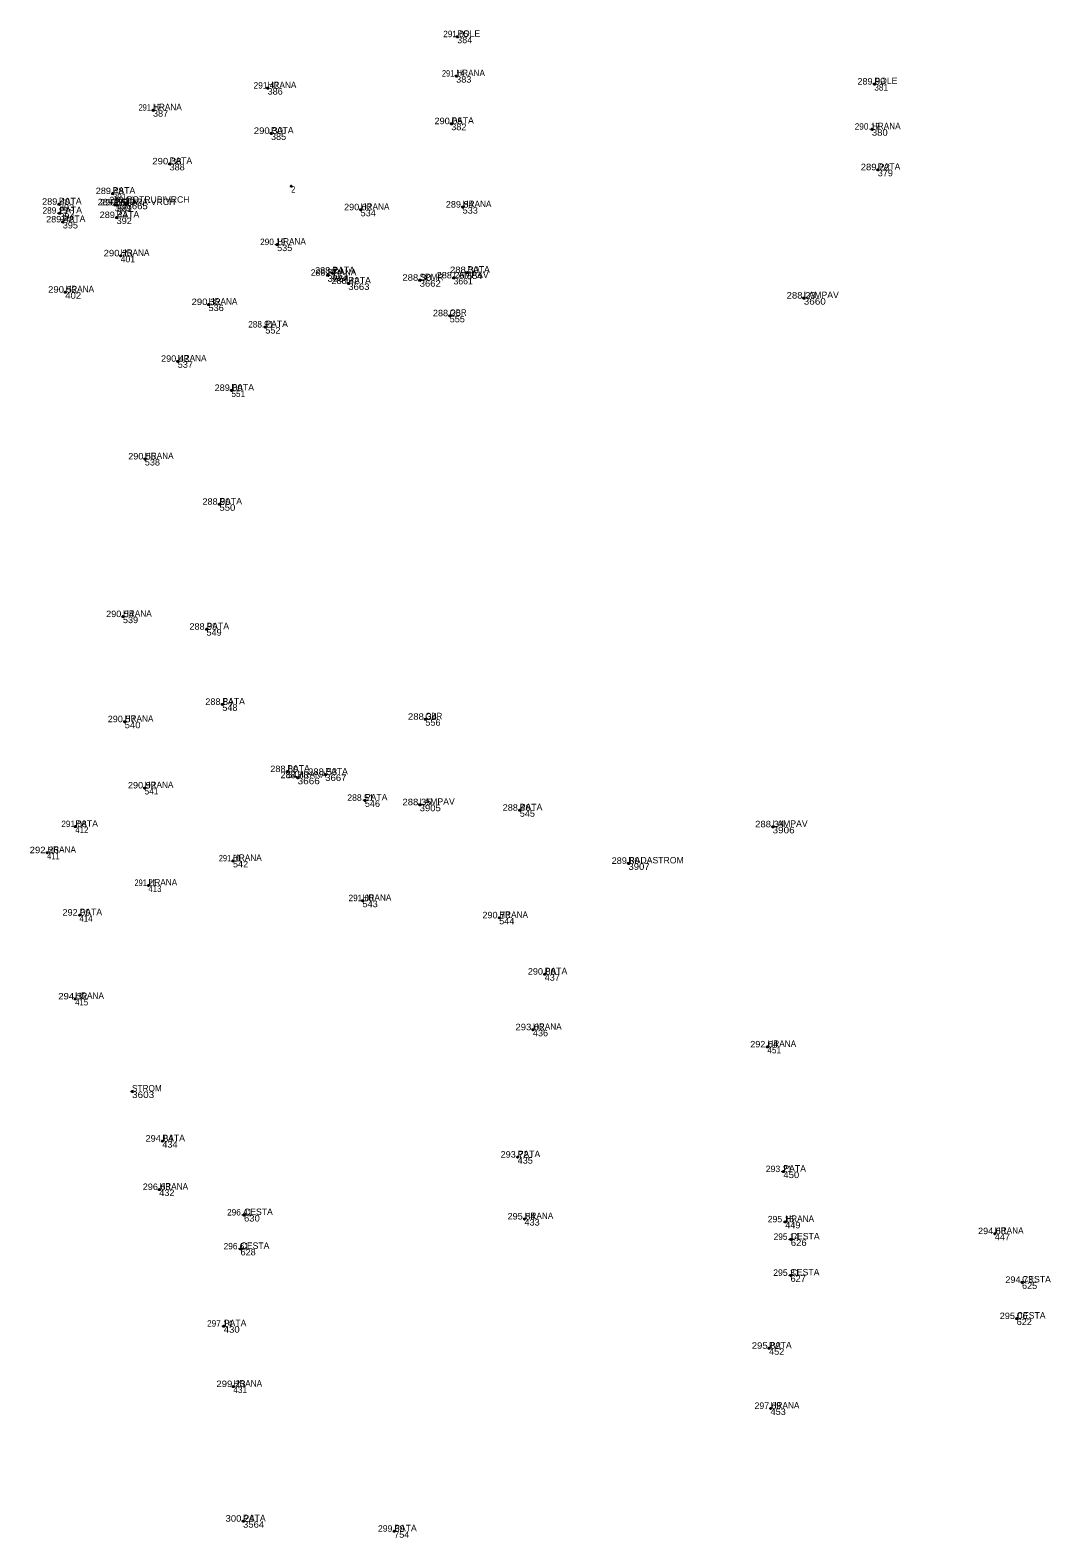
# Model space of a CAD drawing. Extents: x -565336 to -561834, y -1146819 to -1145270.
# Drawn here: x -563802.8 to -563749.2, y -1145852.4 to -1145773.2 of the extents above; entities that cross this region are included whole.
import ezdxf
from ezdxf.enums import TextEntityAlignment as Align

# ---------------------------------------------------------------- set-up
doc = ezdxf.new("R2010")
doc.units = 0
doc.header["$LTSCALE"] = 0.14
doc.header["$PDMODE"] = 32
doc.header["$PDSIZE"] = 0.07
for name, color, linetype in [('40', 7, 'Continuous'), ('43', 7, 'Continuous'), ('44', 7, 'Continuous'), ('45', 7, 'Continuous')]:
    doc.layers.add(name, color=color, linetype=linetype)

msp = doc.modelspace()

# ---------------------------------------------------------------- linework, layer by layer
at = {"layer": '40'}
for p in [(-563780.35, -1145773.53), (-563780.4, -1145775.6), (-563790.31, -1145776.23), (-563758.43, -1145776.02), (-563796.33, -1145777.39), (-563790.13, -1145778.61), (-563780.66, -1145778.1), (-563758.56, -1145778.39), (-563795.46, -1145780.21), (-563758.25, -1145780.52), (-563798.45, -1145781.77), (-563789.07, -1145781.38), (-563801.27, -1145782.33), (-563798.35, -1145782.36), (-563798.24, -1145782.37), (-563797.72, -1145782.25), (-563785.42, -1145782.62), (-563780.06, -1145782.48), (-563801.25, -1145782.8), (-563801.07, -1145783.26), (-563798.24, -1145783.03), (-563798.03, -1145785.04), (-563789.81, -1145784.45), (-563779.82, -1145785.92), (-563787.16, -1145786.06), (-563786.91, -1145785.95), (-563786.07, -1145786.49), (-563782.32, -1145786.32), (-563780.54, -1145786.2), (-563800.94, -1145786.95), (-563762.14, -1145787.26), (-563793.41, -1145787.6), (-563780.74, -1145788.19), (-563790.43, -1145788.78), (-563795.03, -1145790.58), (-563792.21, -1145792.11), (-563796.76, -1145795.71), (-563792.84, -1145798.09), (-563797.91, -1145803.99), (-563793.52, -1145804.65), (-563792.69, -1145808.6), (-563797.82, -1145809.51), (-563782.02, -1145809.38), (-563789.28, -1145812.13), (-563788.73, -1145812.45), (-563787.28, -1145812.28), (-563796.77, -1145812.99), (-563785.2, -1145813.64), (-563782.32, -1145813.87), (-563777.06, -1145814.16), (-563800.41, -1145815.02), (-563763.78, -1145815.03), (-563801.89, -1145816.39), (-563792.13, -1145816.82), (-563771.35, -1145816.95), (-563796.57, -1145818.11), (-563785.32, -1145818.91), (-563800.19, -1145819.67), (-563778.14, -1145819.81), (-563775.75, -1145822.77), (-563800.42, -1145824.07), (-563776.37, -1145825.69), (-563764.05, -1145826.59), (-563797.43, -1145828.93), (-563795.84, -1145831.54), (-563777.17, -1145832.38), (-563763.21, -1145833.14), (-563796, -1145834.08), (-563791.55, -1145835.42), (-563776.81, -1145835.63), (-563763.11, -1145835.78), (-563752.1, -1145836.4), (-563791.73, -1145837.2), (-563762.82, -1145836.7), (-563762.83, -1145838.59), (-563750.67, -1145838.96), (-563792.61, -1145841.26), (-563750.95, -1145840.86), (-563763.96, -1145842.42), (-563792.11, -1145844.43), (-563763.88, -1145845.58), (-563791.6, -1145851.5), (-563783.66, -1145852.03)]:
    msp.add_point(p, dxfattribs=at)

# ---------------------------------------------------------------- texts
at = {"layer": '43'}
for s, width, p in [('384', 1.05, (-563780.35, -1145773.87)), ('383', 1.05, (-563780.4, -1145775.94)), ('386', 1.05, (-563790.31, -1145776.57)), ('381', 0.95, (-563758.43, -1145776.36)), ('387', 1.05, (-563796.33, -1145777.73)), ('385', 1.05, (-563790.13, -1145778.95)), ('382', 1.05, (-563780.66, -1145778.44)), ('380', 1.1, (-563758.56, -1145778.73)), ('388', 1.05, (-563795.46, -1145780.55)), ('379', 1.05, (-563758.25, -1145780.86)), ('391', 0.95, (-563798.45, -1145782.11)), ('2', 0.75, (-563789.07, -1145781.72)), ('393', 1.05, (-563801.27, -1145782.67)), ('390', 1.1, (-563798.35, -1145782.7)), ('389', 1.05, (-563798.24, -1145782.71)), ('3665', 1.1, (-563797.72, -1145782.59)), ('534', 1.05, (-563785.42, -1145782.96)), ('533', 1.05, (-563780.06, -1145782.82)), ('394', 1.05, (-563801.25, -1145783.14)), ('395', 1.05, (-563801.07, -1145783.6)), ('392', 1.05, (-563798.24, -1145783.37)), ('535', 1.05, (-563789.81, -1145784.79)), ('3664', 1.1, (-563787.16, -1145786.4)), ('553', 1.05, (-563786.91, -1145786.29)), ('3663', 1.1, (-563786.07, -1145786.83)), ('3662', 1.1, (-563782.32, -1145786.66)), ('554', 1.05, (-563779.82, -1145786.26)), ('402', 1.1, (-563800.94, -1145787.29)), ('3660', 1.15, (-563762.14, -1145787.6)), ('536', 1.05, (-563793.41, -1145787.94)), ('555', 1.05, (-563780.74, -1145788.53)), ('552', 1.05, (-563790.43, -1145789.12)), ('537', 1.05, (-563795.03, -1145790.92)), ('551', 0.95, (-563792.21, -1145792.45)), ('538', 1.05, (-563796.76, -1145796.05)), ('550', 1.1, (-563792.84, -1145798.43)), ('539', 1.05, (-563797.91, -1145804.33)), ('549', 1.05, (-563793.52, -1145804.99)), ('548', 1.05, (-563792.69, -1145808.94)), ('540', 1.1, (-563797.82, -1145809.85)), ('556', 1.05, (-563782.02, -1145809.72)), ('547', 1.05, (-563789.28, -1145812.47)), ('3666', 1.15, (-563788.73, -1145812.79)), ('3667', 1.1, (-563787.28, -1145812.62)), ('541', 0.95, (-563796.77, -1145813.33)), ('546', 1.05, (-563785.2, -1145813.98)), ('3905', 1.1, (-563782.32, -1145814.21)), ('545', 1.05, (-563777.06, -1145814.5)), ('412', 0.9, (-563800.41, -1145815.36)), ('3906', 1.15, (-563763.78, -1145815.37)), ('411', 0.8, (-563801.89, -1145816.73)), ('542', 1.05, (-563792.13, -1145817.16)), ('3907', 1.1, (-563771.35, -1145817.29)), ('413', 0.9, (-563796.57, -1145818.45)), ('543', 1.05, (-563785.32, -1145819.25)), ('414', 0.9, (-563800.19, -1145820.01)), ('544', 1.05, (-563778.14, -1145820.15)), ('437', 1.05, (-563775.75, -1145823.11)), ('415', 0.9, (-563800.42, -1145824.41)), ('436', 1.05, (-563776.37, -1145826.03)), ('451', 0.95, (-563764.05, -1145826.93)), ('3603', 1.15, (-563797.43, -1145829.27)), ('434', 1.05, (-563795.84, -1145831.88)), ('435', 1.05, (-563777.17, -1145832.72)), ('450', 1.1, (-563763.21, -1145833.48)), ('432', 1.05, (-563796, -1145834.42)), ('630', 1.1, (-563791.55, -1145835.76)), ('433', 1.05, (-563776.81, -1145835.97)), ('449', 1.05, (-563763.11, -1145836.12)), ('447', 1.05, (-563752.1, -1145836.74)), ('628', 1.05, (-563791.73, -1145837.54)), ('626', 1.1, (-563762.82, -1145837.04)), ('627', 1.05, (-563762.83, -1145838.93)), ('625', 1.05, (-563750.67, -1145839.3)), ('430', 1.1, (-563792.61, -1145841.6)), ('622', 1.05, (-563750.95, -1145841.2)), ('452', 1.05, (-563763.96, -1145842.76)), ('431', 0.95, (-563792.11, -1145844.77)), ('453', 1.05, (-563763.88, -1145845.92)), ('3564', 1.1, (-563791.6, -1145851.84)), ('754', 1.05, (-563783.66, -1145852.37))]:
    msp.add_text(s, height=0.34, dxfattribs=dict(at, width=width)).set_placement(p)
for s, p in [('401', (-563798.03, -1145785.38)), ('3661', (-563780.54, -1145786.54))]:
    msp.add_text(s, height=0.34, dxfattribs=at).set_placement(p)
at = {"layer": '44'}
for s, width, p in [('291.05', 0.95, (-563780.421, -1145773.554)), ('291.14', 0.85, (-563780.5555, -1145775.624)), ('291.42', 0.95, (-563790.381, -1145776.254)), ('289.99', 1.05, (-563758.5905, -1145776.044)), ('291.17', 0.85, (-563796.4935, -1145777.414)), ('290.05', 1.05, (-563780.806, -1145778.124)), ('290.30', 1.1, (-563790.268, -1145778.634)), ('290.17', 0.95, (-563758.7985, -1145778.414)), ('290.38', 1.1, (-563795.5995, -1145780.234)), ('289.22', 1.1, (-563758.3815, -1145780.544)), ('289.48', 1.05, (-563798.6065, -1145781.794)), ('290.16', 0.95, (-563797.9505, -1145782.274)), ('289.40', 1.05, (-563801.4255, -1145782.354)), ('289.15', 0.95, (-563801.471, -1145782.824)), ('289.06', 1.05, (-563798.5055, -1145782.384)), ('289.44', 1.05, (-563798.4005, -1145783.054)), ('290.28', 1.05, (-563798.382, -1145782.394)), ('290.02', 1.05, (-563785.5605, -1145782.644)), ('289.84', 1.05, (-563780.2155, -1145782.504)), ('289.42', 1.05, (-563801.216, -1145783.284)), ('290.19', 0.95, (-563790.0405, -1145784.474)), ('290.23', 1.1, (-563798.1585, -1145785.064)), ('288.74', 1.05, (-563787.0845, -1145785.974)), ('288.26', 1.05, (-563780.6915, -1145786.224)), ('288.30', 1.1, (-563779.9635, -1145785.944)), ('290.52', 1.1, (-563801.0765, -1145786.974)), ('288.42', 1.05, (-563786.2215, -1145786.514)), ('288.30', 1.1, (-563782.4635, -1145786.344)), ('290.32', 1.1, (-563793.5385, -1145787.624)), ('288.23', 1.1, (-563762.274, -1145787.284)), ('288.26', 1.05, (-563780.8915, -1145788.214)), ('288.91', 0.95, (-563790.666, -1145788.804)), ('290.42', 1.05, (-563795.176, -1145790.604)), ('289.00', 1.05, (-563792.36, -1145792.134)), ('290.55', 1.05, (-563796.902, -1145795.734)), ('288.90', 1.05, (-563793.001, -1145798.114)), ('290.54', 1.05, (-563798.0615, -1145804.014)), ('288.99', 1.05, (-563793.686, -1145804.674)), ('288.84', 1.05, (-563792.851, -1145808.624)), ('290.57', 1.05, (-563797.9795, -1145809.534)), ('288.34', 1.1, (-563782.169, -1145809.404)), ('288.80', 1.05, (-563789.4355, -1145812.154)), ('288.53', 1.1, (-563787.4195, -1145812.304)), ('290.92', 1.05, (-563796.916, -1145813.014)), ('288.78', 1.05, (-563788.9005, -1145812.474)), ('288.35', 1.1, (-563782.4595, -1145813.894)), ('288.46', 1.05, (-563777.226, -1145814.184)), ('291.08', 0.95, (-563800.4865, -1145815.044)), ('288.34', 1.1, (-563763.929, -1145815.054)), ('292.26', 1.1, (-563802.0455, -1145816.414)), ('291.01', 0.85, (-563792.28, -1145816.844)), ('289.80', 1.05, (-563771.5, -1145816.974)), ('291.21', 0.85, (-563796.7105, -1145818.134)), ('291.00', 0.95, (-563785.395, -1145818.934)), ('292.09', 1.05, (-563800.355, -1145819.694)), ('290.73', 1.05, (-563778.2915, -1145819.834)), ('290.86', 1.05, (-563775.9055, -1145822.794)), ('294.32', 1.1, (-563800.543, -1145824.094)), ('293.02', 1.1, (-563776.5225, -1145825.714)), ('292.64', 1.05, (-563764.22, -1145826.614)), ('294.84', 1.05, (-563795.99, -1145831.564)), ('293.72', 1.05, (-563777.336, -1145832.404)), ('296.63', 1.05, (-563796.138, -1145834.104)), ('296.41', 0.95, (-563791.775, -1145835.444)), ('295.84', 1.05, (-563776.9695, -1145835.654)), ('295.14', 0.95, (-563763.0545, -1145836.724)), ('294.68', 1.05, (-563752.251, -1145836.424)), ('296.61', 0.95, (-563791.955, -1145837.224)), ('294.73', 1.05, (-563750.816, -1145838.984)), ('295.06', 1.05, (-563751.1095, -1145840.884)), ('297.14', 0.95, (-563792.827, -1145841.284)), ('295.82', 1.1, (-563764.1045, -1145842.444)), ('299.23', 1.1, (-563792.233, -1145844.454)), ('300.24', 1.1, (-563791.754, -1145851.524))]:
    msp.add_text(s, height=0.34, dxfattribs=dict(at, width=width)).set_placement(p, align=Align.CENTER)
for s, p in [('288.77', (-563787.3425, -1145786.084)), ('288.51', (-563785.4265, -1145813.664)), ('293.21', (-563763.4375, -1145833.164)), ('295.15', (-563763.335, -1145835.804)), ('295.31', (-563763.047, -1145838.614)), ('297.69', (-563764.027, -1145845.604)), ('299.69', (-563783.815, -1145852.054))]:
    msp.add_text(s, height=0.34, dxfattribs=at).set_placement(p, align=Align.CENTER)
at = {"layer": '45'}
for s, p in [('POLE', (-563780.35, -1145773.53)), ('POLE', (-563758.43, -1145776.02)), ('PATA', (-563780.66, -1145778.1)), ('PATA', (-563790.13, -1145778.61)), ('PATA', (-563795.46, -1145780.21)), ('PATA', (-563758.25, -1145780.52)), ('PATA', (-563798.45, -1145781.77)), ('POTRUBIVRCH', (-563797.72, -1145782.25)), ('PATA', (-563801.27, -1145782.33)), ('PATA', (-563801.25, -1145782.8)), ('PATA', (-563798.35, -1145782.36)), ('ROURA-VRCH', (-563798.24, -1145782.37)), ('PATA', (-563798.24, -1145783.03)), ('PATA', (-563801.07, -1145783.26)), ('PATA', (-563786.91, -1145785.95)), ('LAMPAV', (-563780.54, -1145786.2)), ('PATA', (-563779.82, -1145785.92)), ('PATA', (-563786.07, -1145786.49)), ('LAMPAV', (-563762.14, -1145787.26)), ('PATA', (-563790.43, -1145788.78)), ('PATA', (-563792.21, -1145792.11)), ('PATA', (-563792.84, -1145798.09)), ('PATA', (-563793.52, -1145804.65)), ('PATA', (-563792.69, -1145808.6)), ('PATA', (-563789.28, -1145812.13)), ('PATA', (-563787.28, -1145812.28)), ('PATA', (-563785.2, -1145813.64)), ('LAMPAV', (-563782.32, -1145813.87)), ('PATA', (-563777.06, -1145814.16)), ('PATA', (-563800.41, -1145815.02)), ('LAMPAV', (-563763.78, -1145815.03)), ('RADASTROM', (-563771.35, -1145816.95)), ('PATA', (-563800.19, -1145819.67)), ('PATA', (-563775.75, -1145822.77)), ('PATA', (-563795.84, -1145831.54)), ('PATA', (-563777.17, -1145832.38)), ('PATA', (-563763.21, -1145833.14)), ('CESTA', (-563791.55, -1145835.42)), ('CESTA', (-563762.82, -1145836.7)), ('CESTA', (-563791.73, -1145837.2)), ('CESTA', (-563762.83, -1145838.59)), ('CESTA', (-563750.67, -1145838.96)), ('CESTA', (-563750.95, -1145840.86)), ('PATA', (-563792.61, -1145841.26)), ('PATA', (-563763.96, -1145842.42)), ('PATA', (-563791.6, -1145851.5)), ('PATA', (-563783.66, -1145852.03))]:
    msp.add_text(s, height=0.34, dxfattribs=at).set_placement(p)
for s, width, p in [('HRANA', 0.95, (-563780.4, -1145775.6)), ('HRANA', 0.95, (-563790.31, -1145776.23)), ('HRANA', 0.95, (-563796.33, -1145777.39)), ('HRANA', 0.95, (-563758.56, -1145778.39)), ('HRANA', 0.95, (-563785.42, -1145782.62)), ('HRANA', 0.95, (-563780.06, -1145782.48)), ('HRANA', 0.95, (-563789.81, -1145784.45)), ('HRANA', 0.95, (-563798.03, -1145785.04)), ('HRANA', 0.95, (-563787.16, -1145786.06)), ('HRANA', 0.95, (-563800.94, -1145786.95)), ('SPMR', 0.95, (-563782.32, -1145786.32)), ('HRANA', 0.95, (-563793.41, -1145787.6)), ('OBR', 0.9, (-563780.74, -1145788.19)), ('HRANA', 0.95, (-563795.03, -1145790.58)), ('HRANA', 0.95, (-563796.76, -1145795.71)), ('HRANA', 0.95, (-563797.91, -1145803.99)), ('HRANA', 0.95, (-563797.82, -1145809.51)), ('OBR', 0.9, (-563782.02, -1145809.38)), ('HRANA', 0.95, (-563796.77, -1145812.99)), ('HRANA', 0.95, (-563788.73, -1145812.45)), ('HRANA', 0.95, (-563801.89, -1145816.39)), ('HRANA', 0.95, (-563792.13, -1145816.82)), ('HRANA', 0.95, (-563796.57, -1145818.11)), ('HRANA', 0.95, (-563785.32, -1145818.91)), ('HRANA', 0.95, (-563778.14, -1145819.81)), ('HRANA', 0.95, (-563800.42, -1145824.07)), ('HRANA', 0.95, (-563776.37, -1145825.69)), ('HRANA', 0.95, (-563764.05, -1145826.59)), ('STROM', 0.95, (-563797.43, -1145828.93)), ('HRANA', 0.95, (-563796, -1145834.08)), ('HRANA', 0.95, (-563776.81, -1145835.63)), ('HRANA', 0.95, (-563763.11, -1145835.78)), ('HRANA', 0.95, (-563752.1, -1145836.4)), ('HRANA', 0.95, (-563792.11, -1145844.43)), ('HRANA', 0.95, (-563763.88, -1145845.58))]:
    msp.add_text(s, height=0.34, dxfattribs=dict(at, width=width)).set_placement(p)

doc.saveas('drawing.dxf')
